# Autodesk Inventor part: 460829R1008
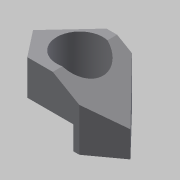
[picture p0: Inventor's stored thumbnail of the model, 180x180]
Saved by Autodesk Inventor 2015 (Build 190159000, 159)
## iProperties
Created: 2016-08
Part Number: 460829R1008
Material: 일반
Document SubType Name: Modeling
Designer: jio
Density: 1 g/cm^3
Appearance: 기본값
Author: jio
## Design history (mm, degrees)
sketch "스케치1"
  geometry: L1 (-9.387, 55)-(34, 55); L2 (34, 55)-(104.673, -18.184); L3 (104.673, -18.184)-(54, -55); L4 (54, -55)-(-34.842, -55); L5 (-34.842, -55)-(-70, -10); L6 (-70, -10)-(-9.387, 55); C1 r 39.5 at (0, 0); 1 further point
  constraints: 12 end point, 1 centre point, 1 coincident, 1 horizontal, 1 parallel
  dimensions: "d0" = 79 diameter of C1; "d1" = 134 deg angle of L2 L1; "d3" = 144 deg angle of L3 L4; "d4" = 99 deg angle of L5 L6; "d5" = 128 deg angle of L4 L5; "d6" = 124 horizontal distance of L3.end L5.end; "d7" = 45 vertical distance of L4.end L5.end; "d8" = 110 vertical distance of L1.start L4.end; "d9" = 104 horizontal distance of L1.end L5.end; "d10" = 55 vertical distance of L3.end point (0, 0); "d11" = 70 horizontal distance of point (0, 0) L5.end
extrude "돌출1" new body sketch "스케치1" distance "d12" = 100; taper "d13" = 0 deg
sketch "스케치2"
  geometry: L1 (-70, 15)-(44, 15); L2 (44, 15)-(44, -55); L3 (44, -55)-(-70, -55); L4 (-70, -55)-(-70, 15); L5 (-34.842, -55)-(54, -55) reference; 2 further points
  constraints: 8 end point, 2 parallel, 1 collinear, 1 horizontal, 1 perpendicular, 1 point on line
  dimensions: "d14" = 114 distance of L2.end L3.end; "d15" = 70 distance of L1.end L2.end
extrude "돌출2" cut sketch "스케치2" distance "d16" = 40; taper "d17" = 0 deg
sketch "스케치3"
  geometry: L1 (43.515, 0)-(139.515, -55.426); L2 (139.515, -55.426)-(139.515, 0); L3 (139.515, 0)-(43.515, 0); 2 further points
  constraints: 6 end point, 1 coincident, 1 perpendicular, 1 vertical
  dimensions: "d18" = 30 deg angle of L1 L3; "d19" = 96 distance of L2.end L1.start
extrude "돌출3" cut sketch "스케치3" stored distance "d20" = 40; taper "d21" = 0 deg
node "솔리드1"
